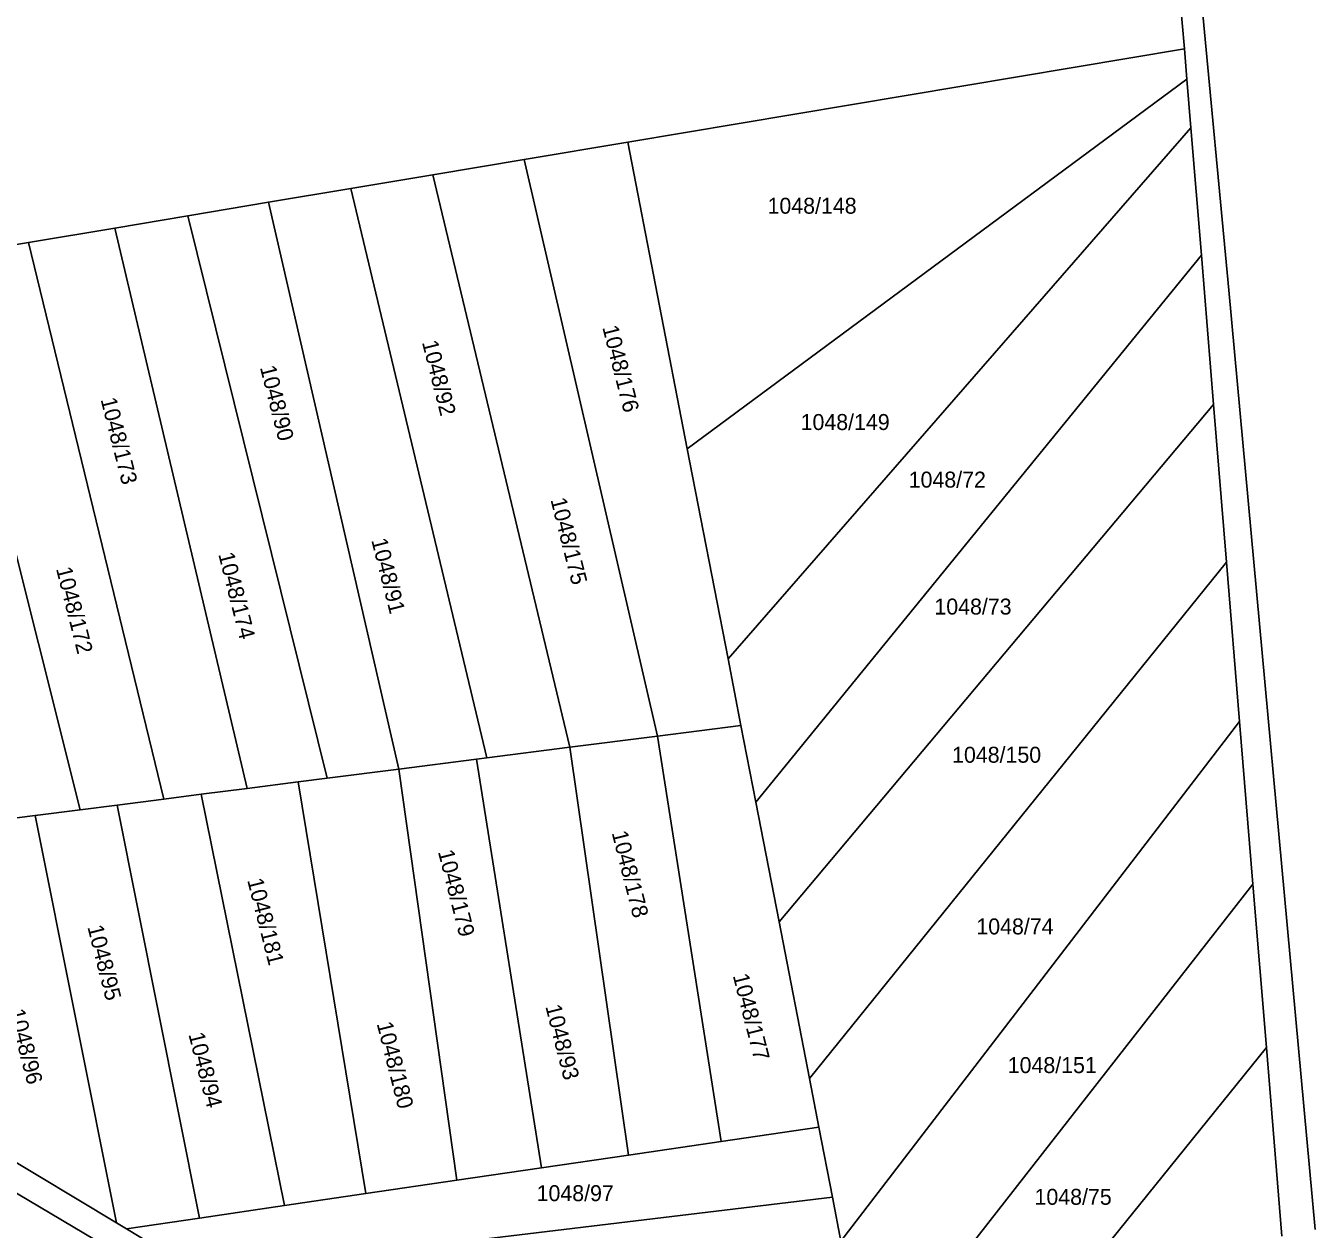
# Model space of a CAD drawing. Extents: x -580630 to -576196, y -1189024 to -1183567.
# Drawn here: x -576999.1 to -576861.8, y -1185871.9 to -1185743.8 of the extents above; entities that cross this region are included whole.
import ezdxf

# ---------------------------------------------------------------- set-up
doc = ezdxf.new("R2010")
doc.units = 0
for name, color, linetype in [('Vrstva 13', 7, 'Continuous'), ('Vrstva 18', 7, 'Continuous'), ('Vrstva 6', 7, 'Continuous')]:
    doc.layers.add(name, color=color, linetype=linetype)

msp = doc.modelspace()

# ---------------------------------------------------------------- linework, layer by layer
at = {"layer": 'Vrstva 13'}
for p, q in [((-576875.47, -1185724.37), (-576870.96, -1185771.95)), ((-576870.96, -1185771.95), (-576861.78, -1185871.95))]:
    msp.add_line(p, q, dxfattribs=at)
at = {"layer": 'Vrstva 6'}
for p, q in [((-576875.7, -1185746.29), (-576877.56, -1185725.95)), ((-576934.97, -1185756.21), (-576875.7, -1185746.29)), ((-576875.7, -1185746.29), (-576875.44, -1185749.5)), ((-576928.64, -1185788.85), (-576875.44, -1185749.5)), ((-576875.44, -1185749.5), (-576875.01, -1185754.68)), ((-576924.3, -1185811.21), (-576875.01, -1185754.68)), ((-576875.01, -1185754.68), (-576873.9, -1185768.23)), ((-576945.99, -1185758.05), (-576934.97, -1185756.21)), ((-576934.97, -1185756.21), (-576928.64, -1185788.85)), ((-576955.73, -1185759.68), (-576945.99, -1185758.05)), ((-576931.81, -1185819.42), (-576945.99, -1185758.05)), ((-577182.94, -1185759.88), (-576902.8, -1185925.6)), ((-576964.47, -1185761.15), (-576955.73, -1185759.68)), ((-576941.14, -1185820.61), (-576955.73, -1185759.68)), ((-576973.24, -1185762.61), (-576964.47, -1185761.15)), ((-576949.96, -1185821.74), (-576964.47, -1185761.15)), ((-576981.8, -1185764.05), (-576973.24, -1185762.61)), ((-576959.35, -1185822.93), (-576973.24, -1185762.61)), ((-576989.6, -1185765.35), (-576981.8, -1185764.05)), ((-576966.99, -1185823.91), (-576981.8, -1185764.05)), ((-576998.79, -1185766.89), (-576989.6, -1185765.35)), ((-576989.6, -1185765.35), (-576975.51, -1185825)), ((-577008.05, -1185768.44), (-576998.79, -1185766.89)), ((-576984.37, -1185826.13), (-576998.79, -1185766.89)), ((-577008.05, -1185768.44), (-576993.27, -1185827.27)), ((-576873.9, -1185768.23), (-576921.34, -1185826.46)), ((-576873.9, -1185768.23), (-576872.6, -1185784.14)), ((-576918.87, -1185839.18), (-576872.6, -1185784.14)), ((-576872.6, -1185784.14), (-576871.22, -1185800.9)), ((-576928.64, -1185788.85), (-576924.3, -1185811.21)), ((-576915.63, -1185855.88), (-576871.22, -1185800.9)), ((-576871.22, -1185800.9), (-576869.83, -1185817.86)), ((-576924.3, -1185811.21), (-576922.93, -1185818.28)), ((-576931.81, -1185819.42), (-576922.93, -1185818.28)), ((-576922.93, -1185818.28), (-576921.34, -1185826.46)), ((-576912.27, -1185873.17), (-576869.83, -1185817.86)), ((-576869.83, -1185817.86), (-576868.41, -1185835.19)), ((-576941.14, -1185820.61), (-576931.81, -1185819.42)), ((-576925.03, -1185862.57), (-576931.81, -1185819.42)), ((-576949.96, -1185821.74), (-576941.14, -1185820.61)), ((-576934.88, -1185864.01), (-576941.14, -1185820.61)), ((-576959.35, -1185822.93), (-576951.09, -1185821.88)), ((-576951.09, -1185821.88), (-576949.96, -1185821.74)), ((-576951.09, -1185821.88), (-576944.15, -1185865.37)), ((-576966.99, -1185823.91), (-576959.35, -1185822.93)), ((-576953.18, -1185866.7), (-576959.35, -1185822.93)), ((-576980.41, -1185825.62), (-576975.51, -1185825)), ((-576975.51, -1185825), (-576970.06, -1185824.3)), ((-576970.06, -1185824.3), (-576966.99, -1185823.91)), ((-576970.06, -1185824.3), (-576962.86, -1185868.12)), ((-576989.33, -1185826.77), (-576984.37, -1185826.13)), ((-576984.37, -1185826.13), (-576980.41, -1185825.62)), ((-576980.41, -1185825.62), (-576971.51, -1185869.39)), ((-576921.34, -1185826.46), (-576918.87, -1185839.18)), ((-577001.68, -1185828.35), (-576998.07, -1185827.89)), ((-576998.07, -1185827.89), (-576993.27, -1185827.27)), ((-576998.07, -1185827.89), (-576989.4, -1185871.23)), ((-576993.27, -1185827.27), (-576989.33, -1185826.77)), ((-576989.33, -1185826.77), (-576980.56, -1185870.72)), ((-576909.46, -1185887.68), (-576868.41, -1185835.19)), ((-576868.41, -1185835.19), (-576866.98, -1185852.58)), ((-576918.87, -1185839.18), (-576915.63, -1185855.88)), ((-576906.72, -1185901.76), (-576866.98, -1185852.58)), ((-576866.98, -1185852.58), (-576865.34, -1185872.63)), ((-576915.63, -1185855.88), (-576914.63, -1185861.04)), ((-576925.03, -1185862.57), (-576914.63, -1185861.04)), ((-576914.63, -1185861.04), (-576913.18, -1185868.51)), ((-577002.18, -1185863.56), (-576989.4, -1185871.23)), ((-576934.88, -1185864.01), (-576925.03, -1185862.57)), ((-576944.15, -1185865.37), (-576934.88, -1185864.01)), ((-576953.18, -1185866.7), (-576944.15, -1185865.37)), ((-576962.86, -1185868.12), (-576953.18, -1185866.7)), ((-576913.18, -1185868.51), (-576980.51, -1185876.57)), ((-576971.51, -1185869.39), (-576962.86, -1185868.12)), ((-576913.18, -1185868.51), (-576912.27, -1185873.17)), ((-576980.56, -1185870.72), (-576971.51, -1185869.39)), ((-576989.4, -1185871.23), (-576988.35, -1185871.86)), ((-576988.35, -1185871.86), (-576980.56, -1185870.72)), ((-576988.35, -1185871.86), (-576980.51, -1185876.57))]:
    msp.add_line(p, q, dxfattribs=at)

# ---------------------------------------------------------------- texts
at = {"layer": 'Vrstva 18'}
for s, p in [('1048/148', (-576920.089, -1185763.83)), ('1048/149', (-576916.568, -1185786.85)), ('1048/72', (-576905.061, -1185792.98)), ('1048/73', (-576902.324, -1185806.49)), ('1048/150', (-576900.442, -1185822.26)), ('1048/74', (-576897.857, -1185840.53)), ('1048/151', (-576894.517, -1185855.29)), ('1048/97', (-576944.677, -1185868.92)), ('1048/75', (-576891.664, -1185869.31))]:
    msp.add_text(s, height=1.7, dxfattribs=at).set_placement(p)
for s, p in [('1048/176', (-576937.691, -1185775.919)), ('1048/92', (-576956.895, -1185777.509)), ('1048/90', (-576974.144, -1185780.185)), ('1048/173', (-576991.112, -1185783.594)), ('1048/175', (-576943.212, -1185794.263)), ('1048/91', (-576962.292, -1185798.568)), ('1048/174', (-576978.581, -1185800.069)), ('1048/172', (-576995.859, -1185801.617)), ('1048/178', (-576936.696, -1185829.709)), ('1048/179', (-576955.191, -1185831.729)), ('1048/181', (-576975.502, -1185834.751)), ('1048/95', (-576992.519, -1185839.735)), ('1048/177', (-576923.801, -1185844.908)), ('1048/96', (-577000.887, -1185848.661)), ('1048/93', (-576943.758, -1185848.196)), ('1048/180', (-576961.714, -1185850.028)), ('1048/94', (-576981.757, -1185851.161))]:
    msp.add_text(s, height=1.7, rotation=284.18707, dxfattribs=at).set_placement(p)

doc.saveas('drawing.dxf')
